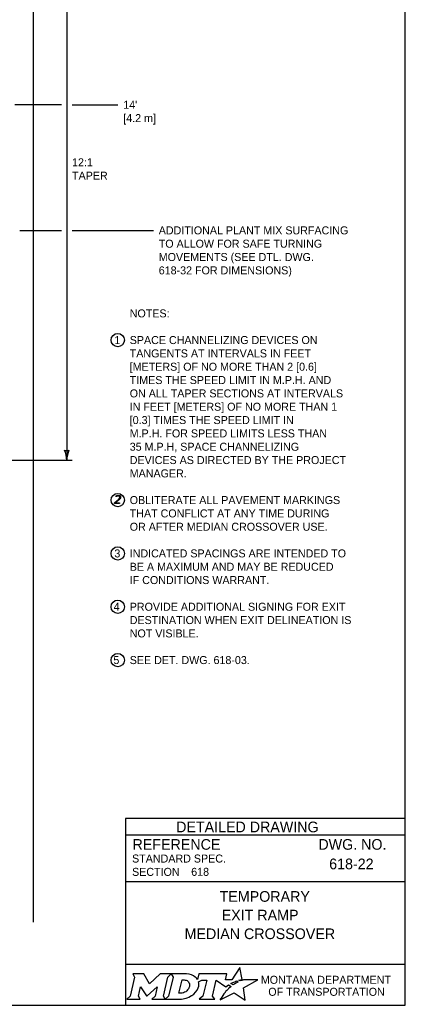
# Model space of a CAD drawing. Extents: x 49991.4 to 50021, y 49987.6 to 50011.4.
# Drawn here: x 50005.72 to 50008.61, y 50000.06 to 50007.45 of the extents above; entities that cross this region are included whole.
import ezdxf

# ---------------------------------------------------------------- set-up
doc = ezdxf.new("R2010")
doc.units = 0
for name, color, linetype in [('Level 1', 7, 'Continuous'), ('Level 2', 7, 'Continuous'), ('Level 3', 7, 'Continuous')]:
    doc.layers.add(name, color=color, linetype=linetype)

msp = doc.modelspace()

# ---------------------------------------------------------------- linework, layer by layer
at = {"layer": 'Level 1'}
msp.add_line((50005.8247, 50000.6846), (50005.8247, 50008.6168), dxfattribs=at)
msp.add_lwpolyline([(50008.6146, 50011.2628), (50000.3356, 50011.2628), (50000.3356, 50000.0624), (50008.6146, 50000.0624)], close=True, dxfattribs=at)
at = {"layer": 'Level 2'}
for p, q in [((50008.6146, 50001.4624), (50006.5146, 50001.4624)), ((50006.5146, 50001.4624), (50006.5146, 50000.0624)), ((50008.6146, 50001.3374), (50006.5146, 50001.3374)), ((50007.0089, 50001.0629), (50007.0089, 50001.0629)), ((50008.2507, 50001.1223), (50008.2507, 50001.1223)), ((50008.6146, 50000.9874), (50006.5146, 50000.9874)), ((50007.5646, 50000.7383), (50007.5646, 50000.7383)), ((50008.6146, 50000.3693), (50006.5146, 50000.3693))]:
    msp.add_line(p, q, dxfattribs=at)
for points in [[(50006.4437, 50003.877), (50006.445, 50003.883)], [(50006.44, 50003.8309), (50006.4707, 50003.8309), (50006.4696, 50003.8259), (50006.4324, 50003.8259), (50006.4336, 50003.8315)], [(50007.3771, 50000.2447), (50007.3668, 50000.2503), (50007.3784, 50000.2531), (50007.39, 50000.2551), (50007.3726, 50000.3452), (50007.3131, 50000.2539), (50007.2658, 50000.2532), (50007.2761, 50000.2973), (50007.0669, 50000.2974), (50007.0568, 50000.2549), (50007.051, 50000.2632)], [(50006.5701, 50000.2974), (50006.5842, 50000.274), (50006.5507, 50000.1307), (50006.525, 50000.1082), (50006.6266, 50000.1082), (50006.6131, 50000.131), (50006.6293, 50000.2011), (50006.673, 50000.1321), (50006.6783, 50000.1321), (50006.7534, 50000.2016), (50006.737, 50000.1305), (50006.7123, 50000.1085), (50006.8139, 50000.1085), (50006.8001, 50000.1318), (50006.8333, 50000.2742)], [(50006.8333, 50000.2742), (50006.8586, 50000.2974), (50006.7762, 50000.2974), (50006.6966, 50000.2244), (50006.6521, 50000.2971), (50006.5701, 50000.2974)], [(50006.9722, 50000.2974), (50006.8586, 50000.2974), (50006.8733, 50000.2745), (50006.8394, 50000.1307), (50006.8139, 50000.1085), (50006.9245, 50000.1085)], [(50006.9962, 50000.2107), (50006.995, 50000.2026), (50006.9918, 50000.1933), (50006.9876, 50000.1851), (50006.982, 50000.1776), (50006.9755, 50000.1707), (50006.9676, 50000.1644), (50006.9593, 50000.1597), (50006.9502, 50000.1558), (50006.9411, 50000.1535), (50006.9319, 50000.1526), (50006.916, 50000.1526), (50006.9396, 50000.2526), (50006.9556, 50000.2526), (50006.9632, 50000.252), (50006.9708, 50000.2501), (50006.9774, 50000.2471), (50006.9835, 50000.2429), (50006.9883, 50000.2379), (50006.992, 50000.2319), (50006.9947, 50000.2257), (50006.9963, 50000.2183), (50006.9963, 50000.2153), (50006.9962, 50000.2107)], [(50007.0636, 50000.2383), (50007.0882, 50000.2514), (50007.1251, 50000.2514), (50007.0965, 50000.1309), (50007.069, 50000.1082), (50007.1852, 50000.1082), (50007.1682, 50000.1311), (50007.1964, 50000.2513), (50007.2677, 50000.1996), (50007.2888, 50000.2147), (50007.3085, 50000.2038)], [(50007.2527, 50000.1479), (50007.2374, 50000.1235), (50007.2327, 50000.116), (50007.2269, 50000.1074), (50007.2246, 50000.1031), (50007.3299, 50000.1562), (50007.4138, 50000.1011), (50007.4007, 50000.1938), (50007.5076, 50000.2522), (50007.4583, 50000.253), (50007.4282, 50000.2534), (50007.4074, 50000.2537), (50007.4006, 50000.2522), (50007.3957, 50000.251), (50007.3873, 50000.2487), (50007.3771, 50000.2447)], [(50007.3267, 50000.2171), (50007.3243, 50000.2154), (50007.306, 50000.225), (50007.3163, 50000.2307), (50007.3204, 50000.2329), (50007.329, 50000.2369), (50007.3347, 50000.2395), (50007.3426, 50000.2425), (50007.3499, 50000.2452), (50007.3617, 50000.2378), (50007.3577, 50000.2357), (50007.3531, 50000.2332), (50007.3489, 50000.231), (50007.3439, 50000.2281), (50007.342, 50000.227), (50007.3393, 50000.2254), (50007.3368, 50000.224), (50007.3345, 50000.2224), (50007.3319, 50000.2206), (50007.3292, 50000.2188), (50007.3267, 50000.2171)], [(50006.9702, 50000.1158), (50006.9786, 50000.1184), (50006.9916, 50000.1238), (50007.012, 50000.1348)], [(50007.2666, 50000.164), (50007.2666, 50000.164)]]:
    msp.add_lwpolyline(points, dxfattribs=at)
for centre in [(50006.4574, 50005.0514), (50006.4574, 50003.8514), (50006.4574, 50003.4513), (50006.4574, 50003.0514), (50006.4574, 50002.6514)]:
    msp.add_circle(centre, 0.05, dxfattribs=at)
for centre, radius, start, end in [((50006.9953, 50000.219), 0.0709, 339.53292, 15.85821), ((50006.9513, 50000.2363), 0.1183, 300.91025, 339.13831)]:
    msp.add_arc(centre, radius, start, end, dxfattribs=at)
for centre, major_axis, ratio, start_param, end_param in [((50006.9701, 50000.25), (0.0834, -0.0037), 0.568097, 0.61298, 1.570796), ((50007.0257, 50000.2573), (0.0361, -0.0295), 0.469099, 1.225588, 1.570796), ((50007.2764, 50000.1742), (-0.0098, -0.0102), 0.016458, 3.141593, 6.279097), ((50007.2974, 50000.1941), (-0.0112, -0.0097), 0.021651, 3.157348, 6.283185), ((50006.9248, 50000.2568), (0, 0.1484), 0.987302, 3.139398, 3.456847), ((50007.2597, 50000.1559), (-0.00694, -0.00806), 0.008222, 0, 3.137361)]:
    msp.add_ellipse(centre, major_axis=major_axis, ratio=ratio, start_param=start_param, end_param=end_param, dxfattribs=at)
for points in [[(50006.4336, 50003.8315), (50006.4391, 50003.8361), (50006.4491, 50003.8444), (50006.459, 50003.8527), (50006.4617, 50003.8551), (50006.4668, 50003.8598), (50006.4692, 50003.8631), (50006.4716, 50003.8664), (50006.4723, 50003.8696), (50006.4726, 50003.8711), (50006.4726, 50003.8724), (50006.4726, 50003.8759), (50006.4704, 50003.8784), (50006.4673, 50003.8818), (50006.4613, 50003.8818), (50006.4572, 50003.8818), (50006.4524, 50003.8804), (50006.4477, 50003.879), (50006.4437, 50003.877)], [(50006.445, 50003.883), (50006.4497, 50003.8847), (50006.4542, 50003.8858), (50006.4587, 50003.8868), (50006.4622, 50003.8868), (50006.4715, 50003.8868), (50006.4759, 50003.8823), (50006.4791, 50003.8789), (50006.4791, 50003.8739), (50006.4791, 50003.8722), (50006.4787, 50003.8702), (50006.4779, 50003.8666), (50006.4759, 50003.8633), (50006.4738, 50003.8601), (50006.4692, 50003.8555), (50006.468, 50003.8544), (50006.4612, 50003.8486), (50006.4545, 50003.8429), (50006.44, 50003.8309)]]:
    msp.add_open_spline(points, degree=3, dxfattribs=at)
at = {"layer": 'Level 3'}
for p, q in [((50006.0747, 50007.5199), (50006.0747, 50006.6372)), ((50006.0347, 50006.816), (50005.6844, 50006.816)), ((50006.1147, 50006.816), (50006.4589, 50006.816)), ((50006.0747, 50006.6372), (50006.0747, 50006.0862)), ((50006.0747, 50006.0862), (50006.0747, 50004.1495)), ((50005.7221, 50005.8741), (50006.0347, 50005.8741)), ((50006.1147, 50005.8741), (50006.7251, 50005.8741)), ((50004.0147, 50004.1495), (50006.1147, 50004.1495))]:
    msp.add_line(p, q, dxfattribs=at)
for centre, radius, start, end in [((50005.8526, 50004.1403), 0.2223, 2.36048, 22.54399), ((50006.0747, 50004.2777), 0.0548, 252.13882, 287.86118), ((50006.3074, 50004.138), 0.233, 157.92284, 177.17269)]:
    msp.add_arc(centre, radius, start, end, dxfattribs=at)

# ---------------------------------------------------------------- texts
at = {"layer": 'Level 2'}
for s, height, p in [("14'", 0.06, (50006.4989, 50006.786)), ('[4.2 m]', 0.06, (50006.4989, 50006.686)), ('12:1', 0.06, (50006.1147, 50006.3543)), ('TAPER', 0.06, (50006.1147, 50006.2543)), ('ADDITIONAL PLANT MIX SURFACING', 0.06, (50006.7651, 50005.8441)), ('TO ALLOW FOR SAFE TURNING', 0.06, (50006.7651, 50005.7441)), ('MOVEMENTS (SEE DTL. DWG. ', 0.06, (50006.7651, 50005.6441)), ('618-32 FOR DIMENSIONS)', 0.06, (50006.7651, 50005.5441)), ('NOTES:', 0.06, (50006.5474, 50005.2214)), ('1', 0.06, (50006.4323, 50005.0214)), ('SPACE CHANNELIZING DEVICES ON', 0.06, (50006.5474, 50005.0214)), ('TANGENTS AT INTERVALS IN FEET', 0.06, (50006.5474, 50004.9214)), ('[METERS] OF NO MORE THAN 2 [0.6]', 0.06, (50006.5474, 50004.8214)), ('TIMES THE SPEED LIMIT IN M.P.H. AND', 0.06, (50006.5474, 50004.7214)), ('ON ALL TAPER SECTIONS AT INTERVALS', 0.06, (50006.5474, 50004.6214)), ('IN FEET [METERS] OF NO MORE THAN 1', 0.06, (50006.5474, 50004.5214)), ('[0.3] TIMES THE SPEED LIMIT IN', 0.06, (50006.5474, 50004.4214)), ('M.P.H. FOR SPEED LIMITS LESS THAN', 0.06, (50006.5474, 50004.3214)), ('35 M.P.H, SPACE CHANNELIZING', 0.06, (50006.5474, 50004.2214)), ('DEVICES AS DIRECTED BY THE PROJECT', 0.06, (50006.5474, 50004.1214)), ('MANAGER.', 0.06, (50006.5474, 50004.0214)), ('OBLITERATE ALL PAVEMENT MARKINGS', 0.06, (50006.5474, 50003.8214)), ('THAT CONFLICT AT ANY TIME DURING', 0.06, (50006.5474, 50003.7214)), ('OR AFTER MEDIAN CROSSOVER USE.', 0.06, (50006.5474, 50003.6214)), ('3', 0.06, (50006.4322, 50003.4213)), ('INDICATED SPACINGS ARE INTENDED TO', 0.06, (50006.5474, 50003.4214)), ('BE A MAXIMUM AND MAY BE REDUCED', 0.06, (50006.5474, 50003.3214)), ('IF CONDITIONS WARRANT.', 0.06, (50006.5474, 50003.2214)), ('4', 0.06, (50006.4267, 50003.0216)), ('PROVIDE ADDITIONAL SIGNING FOR EXIT', 0.06, (50006.5474, 50003.0214)), ('DESTINATION WHEN EXIT DELINEATION IS', 0.06, (50006.5474, 50002.9214)), ('NOT VISIBLE.', 0.06, (50006.5474, 50002.8214)), ('5', 0.06, (50006.4248, 50002.6216)), ('SEE DET. DWG. 618-03.', 0.06, (50006.5474, 50002.6214)), ('DETAILED DRAWING', 0.0799, (50006.8956, 50001.3599)), ('REFERENCE', 0.08, (50006.5682, 50001.229)), ('DWG. NO.', 0.08, (50007.9624, 50001.229)), ('STANDARD SPEC.', 0.06, (50006.5649, 50001.133)), ('618-22', 0.08, (50008.0437, 50001.0827)), ('SECTION', 0.06, (50006.5649, 50001.033)), ('618', 0.06, (50007.0085, 50001.0333)), ('TEMPORARY', 0.08, (50007.2215, 50000.8387)), ('EXIT RAMP', 0.08, (50007.2371, 50000.6987)), ('MEDIAN CROSSOVER', 0.08, (50006.959, 50000.5587)), ('MONTANA DEPARTMENT', 0.06, (50007.5308, 50000.2236)), ('OF TRANSPORTATION', 0.06, (50007.587, 50000.1336))]:
    msp.add_text(s, height=height, dxfattribs=at).set_placement(p)

doc.saveas('drawing.dxf')
